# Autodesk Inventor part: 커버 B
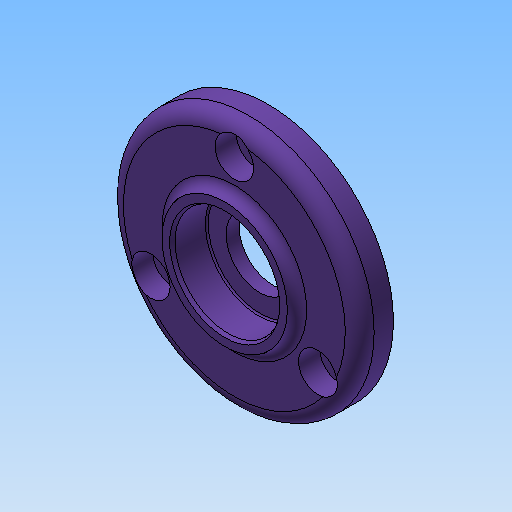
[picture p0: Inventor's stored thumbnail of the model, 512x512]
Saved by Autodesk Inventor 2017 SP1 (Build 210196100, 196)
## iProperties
Created: 2020-04
Part Number: 커버 B
Material: 알루미늄 6061
Document SubType Name: Modeling
Designer: mduedu
Density: 2.71 g/cm^3
Mass: 35.0669 g
Surface Area: 63.5386 cm^2
Volume: 12.9398 cm^3
Appearance: 보라색
Author: mduedu
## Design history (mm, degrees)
sketch "스케치1"
  geometry: C1 r 26 at (0, 0); 1 further point
  constraints: 1 centre point, 1 coincident
  dimensions: "d0" = 52 diameter of C1
extrude "돌출1" new body sketch "스케치1" distance "d1" = 7; taper "d2" = 0 deg
sketch "스케치6"
  geometry: C1 r 13 at (0, 0); 1 further point
  constraints: 1 centre point, 1 coincident
  dimensions: "d29" = 26 diameter of C1
extrude "돌출5" join sketch "스케치6" distance "d30" = 2; taper "d31" = 0 deg
fillet "모깎기2" dims "d7" = 3
fillet "모깎기4" dims "d33" = 2
sketch "스케치3" dims "d8" = 40
  geometry: 3 further points
  constraints: 2 vertical alignment, 1 coincident, 2 other
hole "구멍1" sketch "스케치3" at (0, 20) diameter "d9" = 4.5; stored, may be unused: countersink angle "d13" = 90 deg, drill point angle "d15" = 118 deg; dims "d10" = 6, "d11" = 8, "d12" = 4.4, "d14" = 8
sketch "스케치4"
  geometry: C1 r 14 at (0, 0); 1 further point
  constraints: 1 centre point, 1 coincident
  dimensions: "d19" = 28 diameter of C1
extrude "돌출3" join sketch "스케치4" distance "d20" = 4; taper "d21" = 0 deg
sketch "스케치5"
  geometry: C1 r 12 at (0, 0); 1 further point
  constraints: 1 centre point, 1 coincident
  dimensions: "d22" = 24 diameter of C1
extrude "돌출4" cut sketch "스케치5" distance "d23" = 3; taper "d24" = 0 deg
fillet "모깎기3" dims "d25" = 3
chamfer "모따기1" distance "d26" = 0.5; stored, may be unused: second distance "d27" = 2, angle "d28" = 45 deg
sketch "스케치7"
  geometry: 2 further points
  constraints: 1 coincident
hole "구멍2" sketch "스케치7" at (0, 0) diameter "d34" = 14; stored, may be unused: countersink angle "d38" = 90 deg, drill point angle "d40" = 118 deg; dims "d35" = 6, "d36" = 22, "d37" = 7.3, "d39" = 8
fillet "모깎기5" dims "d41" = 0.3
chamfer "모따기2" distance "d42" = 0.7; stored, may be unused: second distance "d43" = 2, angle "d44" = 30 deg
node "솔리드1"
pattern_circular "원형 패턴1" dims angle "d17" = 360 deg
